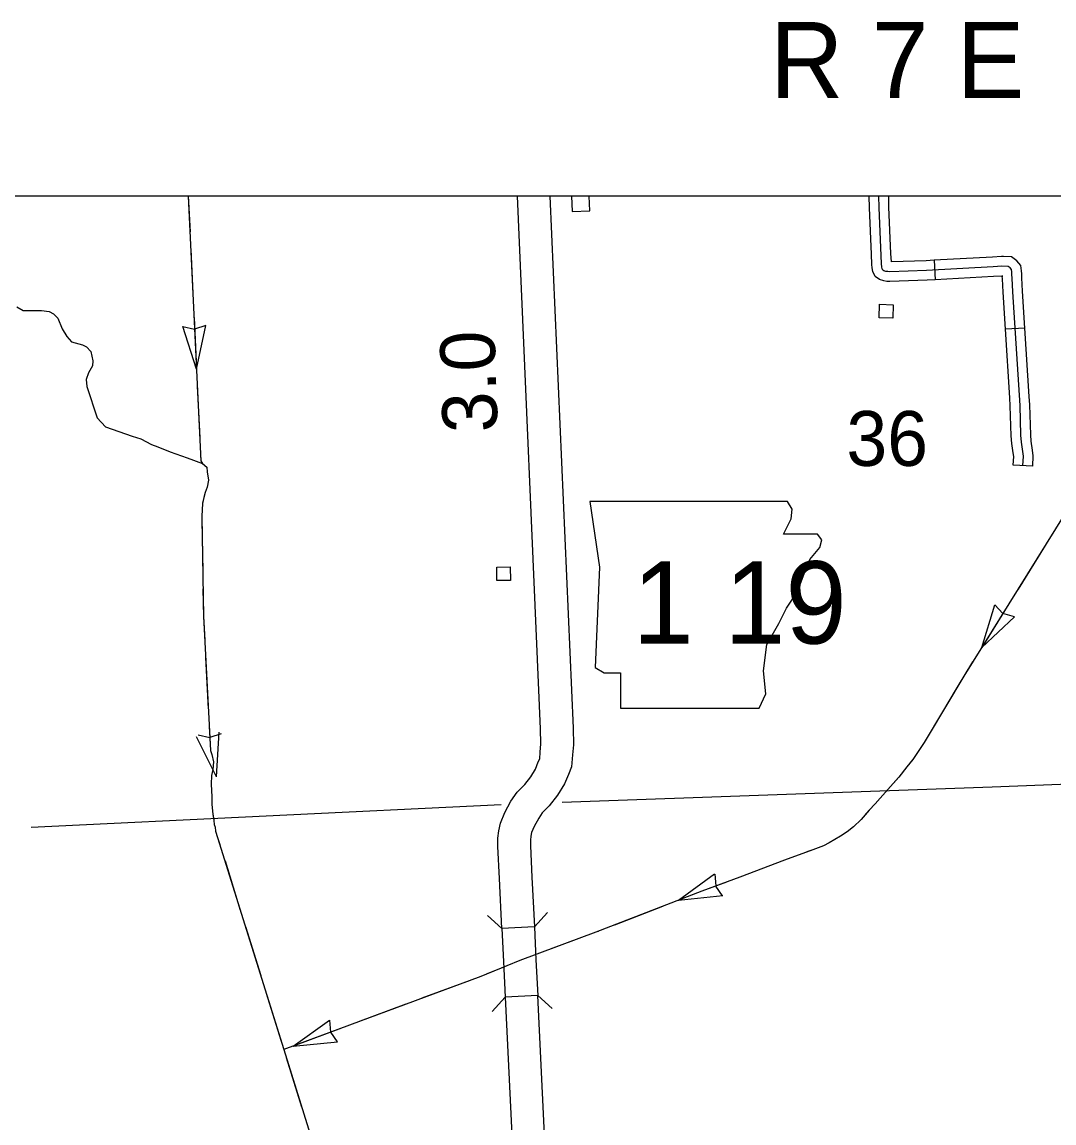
# Model space of a CAD drawing. Extents: x -0.3 to 2.65, y 0 to 1.9.
# Drawn here: x 0.767 to 0.8619, y 0.4564 to 0.5577 of the extents above; entities that cross this region are included whole.
import ezdxf

# ---------------------------------------------------------------- set-up
doc = ezdxf.new("R2010")
doc.units = 0
for name, color, linetype in [('DSN_DRFT_DNC', 7, 'Continuous'), ('Level 11', 7, 'Continuous'), ('Level 12', 7, 'Continuous'), ('Level 13', 7, 'Continuous'), ('Level 14', 7, 'Continuous'), ('Level 16', 7, 'Continuous'), ('Level 19', 7, 'Continuous'), ('Level 20', 7, 'Continuous'), ('Level 21', 7, 'Continuous'), ('Level 22', 7, 'Continuous'), ('Level 30', 7, 'Continuous'), ('Level 31', 7, 'Continuous'), ('Level 6', 7, 'Continuous'), ('SHET_Annotations', 7, 'Continuous')]:
    doc.layers.add(name, color=color, linetype=linetype)

msp = doc.modelspace()

# ---------------------------------------------------------------- linework, layer by layer
at = {"layer": 'DSN_DRFT_DNC'}
msp.add_lwpolyline([(0.38477, 0.54167), (1.0319, 0.54167), (1.0319, 0.1443), (0.38477, 0.1443)], close=True, dxfattribs=at)
at = {"layer": 'Level 11'}
for points in [[(0.81668, 0.4859), (0.85625, 0.4873), (0.87357, 0.48799)], [(0.7678, 0.48359), (0.81108, 0.48569)]]:
    msp.add_lwpolyline(points, dxfattribs=at)
at = {"layer": 'Level 12'}
for p, q in [((0.78227, 0.54164), (0.78243, 0.53836)), ((0.7839, 0.52975), (0.78285, 0.52942)), ((0.78302, 0.52574), (0.7839, 0.52975)), ((0.78302, 0.52574), (0.78177, 0.52965)), ((0.78177, 0.52965), (0.78284, 0.52942)), ((0.8553, 0.50013), (0.85649, 0.50406)), ((0.85649, 0.50406), (0.85724, 0.50326)), ((0.8553, 0.50013), (0.8583, 0.50294)), ((0.8583, 0.50294), (0.85725, 0.50326)), ((0.78486, 0.48823), (0.78512, 0.49233)), ((0.78486, 0.48823), (0.78304, 0.49191)), ((0.78318, 0.49208), (0.78425, 0.49185)), ((0.7853, 0.49219), (0.78426, 0.49185)), ((0.82738, 0.47687), (0.83069, 0.4793)), ((0.83072, 0.47928), (0.83082, 0.47819)), ((0.83145, 0.47728), (0.83082, 0.47818)), ((0.82738, 0.47687), (0.83146, 0.47732)), ((0.79192, 0.46346), (0.79527, 0.46583)), ((0.79527, 0.46583), (0.79537, 0.46475)), ((0.79601, 0.46384), (0.79538, 0.46473)), ((0.79192, 0.46346), (0.79601, 0.46384))]:
    msp.add_line(p, q, dxfattribs=at)
for points in [[(0.78227, 0.54164), (0.78342, 0.51731), (0.78358, 0.51704), (0.78397, 0.51671), (0.78402, 0.51627), (0.78412, 0.51553), (0.78402, 0.51488), (0.78381, 0.51437), (0.78371, 0.51391), (0.78358, 0.51337), (0.78352, 0.51221), (0.78366, 0.50299), (0.78432, 0.49065), (0.78445, 0.49027), (0.78458, 0.48962), (0.78454, 0.48889), (0.78441, 0.48835), (0.78439, 0.48754), (0.78445, 0.48639), (0.78445, 0.48567), (0.78453, 0.48479), (0.78462, 0.48422), (0.78464, 0.48385), (0.78475, 0.48358), (0.78478, 0.48323), (0.78497, 0.48265), (0.79106, 0.46314), (0.79518, 0.44993)], [(0.7825, 0.53678), (0.78272, 0.53205)], [(0.7828, 0.53047), (0.78302, 0.52574)], [(0.78309, 0.52416), (0.78321, 0.52179)], [(0.78321, 0.52179), (0.78332, 0.51942)], [(0.78339, 0.51785), (0.78342, 0.51731), (0.78358, 0.51704), (0.78397, 0.51671), (0.78402, 0.51627), (0.78412, 0.51553), (0.78402, 0.51488), (0.78381, 0.51437), (0.78371, 0.51391), (0.78359, 0.51342)], [(0.86537, 0.51631), (0.85366, 0.4975), (0.84999, 0.49139), (0.84895, 0.48983), (0.84839, 0.48914), (0.84768, 0.4882), (0.84665, 0.48705), (0.84549, 0.48573), (0.84494, 0.48515), (0.84419, 0.48431), (0.84349, 0.48363), (0.8429, 0.48316), (0.8423, 0.48276), (0.84125, 0.48215), (0.84074, 0.48189), (0.83976, 0.48152), (0.83715, 0.48056), (0.83303, 0.479), (0.82953, 0.47771), (0.81979, 0.47393), (0.81278, 0.47132), (0.8092, 0.46986), (0.79106, 0.46314)], [(0.78353, 0.51184), (0.7836, 0.50711)], [(0.86114, 0.50952), (0.85864, 0.5055)], [(0.78362, 0.50553), (0.78366, 0.50299), (0.78378, 0.50079)], [(0.8578, 0.50415), (0.8553, 0.50013)], [(0.78386, 0.49921), (0.78411, 0.49448)], [(0.85446, 0.49879), (0.85366, 0.4975), (0.85322, 0.49677)], [(0.85322, 0.49677), (0.852, 0.49474)], [(0.85119, 0.49339), (0.84999, 0.49139), (0.84895, 0.48983), (0.84861, 0.48941)], [(0.7842, 0.4929), (0.78432, 0.49065), (0.78445, 0.49027), (0.78458, 0.48962), (0.78454, 0.48889), (0.78441, 0.48835), (0.78441, 0.48822)], [(0.84765, 0.48817), (0.84665, 0.48705), (0.84549, 0.48573), (0.84494, 0.48515), (0.84448, 0.48464)], [(0.78444, 0.48664), (0.78445, 0.48639), (0.78445, 0.48567), (0.78453, 0.48479), (0.78461, 0.48428)], [(0.78461, 0.48428), (0.78462, 0.48422), (0.78464, 0.48385), (0.78475, 0.48358), (0.78478, 0.48323), (0.78497, 0.48265), (0.78517, 0.482)], [(0.84336, 0.48353), (0.8429, 0.48316), (0.8423, 0.48276), (0.84125, 0.48215), (0.84074, 0.48189), (0.83976, 0.48152), (0.8392, 0.48132)], [(0.78565, 0.48049), (0.78706, 0.47597)], [(0.83772, 0.48077), (0.83715, 0.48056), (0.83329, 0.4791)], [(0.83181, 0.47855), (0.82953, 0.47771), (0.82738, 0.47687)], [(0.8259, 0.4763), (0.8237, 0.47544)], [(0.8237, 0.47544), (0.82149, 0.47459)], [(0.78753, 0.47446), (0.78894, 0.46994)], [(0.82001, 0.47401), (0.81979, 0.47393), (0.81557, 0.47236)], [(0.81131, 0.47072), (0.80969, 0.47006)], [(0.80821, 0.4695), (0.80377, 0.46785)], [(0.78941, 0.46843), (0.79082, 0.4639)], [(0.80229, 0.4673), (0.79785, 0.46565)], [(0.79637, 0.46511), (0.79192, 0.46346)], [(0.79129, 0.4624), (0.7927, 0.45787)]]:
    msp.add_lwpolyline(points, dxfattribs=at)
at = {"layer": 'Level 13'}
for p, q in [((0.85092, 0.53575), (0.85101, 0.53396)), ((0.85927, 0.52951), (0.85748, 0.5294)), ((0.85999, 0.51681), (0.8582, 0.5169))]:
    msp.add_line(p, q, dxfattribs=at)
for points in [[(0.84515, 0.5363), (0.84497, 0.54057), (0.84493, 0.54164)], [(0.85909, 0.51685), (0.85914, 0.51773), (0.85909, 0.51816), (0.85896, 0.519), (0.8589, 0.51965), (0.85882, 0.5224), (0.85817, 0.53285), (0.85811, 0.53409), (0.85808, 0.53444), (0.85807, 0.53469), (0.85804, 0.53489), (0.85791, 0.53504), (0.85773, 0.53517), (0.85713, 0.5352), (0.85634, 0.53515), (0.85021, 0.53481), (0.84685, 0.53469), (0.84665, 0.5347), (0.84648, 0.53472), (0.84629, 0.53478), (0.84619, 0.53485), (0.84613, 0.53497), (0.84611, 0.53515), (0.84608, 0.53543), (0.84587, 0.5406), (0.84583, 0.54164)], [(0.84694, 0.53638), (0.84676, 0.54064), (0.84673, 0.54164)], [(0.85101, 0.53396), (0.85026, 0.53392), (0.84684, 0.53379), (0.84655, 0.5338), (0.84628, 0.53385), (0.84589, 0.53397), (0.84548, 0.53425), (0.84526, 0.53471), (0.84522, 0.53505), (0.84519, 0.53537), (0.84515, 0.5363)], [(0.85092, 0.53575), (0.85017, 0.53571), (0.84698, 0.53559), (0.84694, 0.53638)], [(0.85731, 0.53609), (0.85712, 0.53609), (0.85629, 0.53604), (0.85092, 0.53575)], [(0.85927, 0.52951), (0.85906, 0.5329), (0.859, 0.53414), (0.85898, 0.53449), (0.85896, 0.53479), (0.85888, 0.53528), (0.85852, 0.5357), (0.85804, 0.53606), (0.85731, 0.53609)], [(0.85724, 0.53429), (0.85714, 0.5343), (0.85639, 0.53425), (0.85101, 0.53396)], [(0.85748, 0.5294), (0.85727, 0.5328), (0.85721, 0.53404), (0.85719, 0.53429), (0.85724, 0.53429)], [(0.85787, 0.5231), (0.85748, 0.5294)], [(0.85966, 0.52321), (0.85927, 0.52951)], [(0.8582, 0.5169), (0.85824, 0.51771), (0.8582, 0.51804), (0.85806, 0.51889), (0.85801, 0.5196), (0.85792, 0.52236), (0.85787, 0.5231)], [(0.85999, 0.51681), (0.86004, 0.51776), (0.85998, 0.51828), (0.85985, 0.51911), (0.8598, 0.5197), (0.85971, 0.52244), (0.85966, 0.52321)]]:
    msp.add_lwpolyline(points, dxfattribs=at)
at = {"layer": 'Level 14'}
msp.add_lwpolyline([(0.7665, 0.53147), (0.76707, 0.53112), (0.76796, 0.53112), (0.76877, 0.53112), (0.76946, 0.53104), (0.76988, 0.53083), (0.77026, 0.53042), (0.77067, 0.52945), (0.77108, 0.52874), (0.77151, 0.52824), (0.77252, 0.52796), (0.7729, 0.52777), (0.7733, 0.52734), (0.77349, 0.52651), (0.77347, 0.52603), (0.77309, 0.52538), (0.77286, 0.52477), (0.77294, 0.52415), (0.77389, 0.52125), (0.77464, 0.52042), (0.7771, 0.51958), (0.7779, 0.51932), (0.77889, 0.51881), (0.77946, 0.51857), (0.7806, 0.51812), (0.78218, 0.51757), (0.78358, 0.51704)], dxfattribs=at)
at = {"layer": 'Level 19'}
for points in [[(0.84714, 0.53166), (0.8471, 0.53042), (0.84585, 0.53046), (0.8459, 0.53171)], [(0.81191, 0.50754), (0.81193, 0.50629), (0.81068, 0.50628), (0.81067, 0.50752)]]:
    msp.add_lwpolyline(points, close=True, dxfattribs=at)
at = {"layer": 'Level 21'}
for points in [[(0.81113, 0.47427), (0.8109, 0.47887), (0.81076, 0.48181), (0.81076, 0.48257), (0.81084, 0.48325), (0.81099, 0.48397), (0.81139, 0.48495), (0.81197, 0.48599), (0.81253, 0.48682), (0.81323, 0.48753), (0.81379, 0.48824), (0.81422, 0.48893), (0.81448, 0.4896), (0.81461, 0.48989), (0.81466, 0.49049), (0.81471, 0.49126), (0.8147, 0.49263), (0.81256, 0.54164)], [(0.81555, 0.54164), (0.81769, 0.49271), (0.81771, 0.49118), (0.81764, 0.49026), (0.81755, 0.48915), (0.81725, 0.48845), (0.8169, 0.48758), (0.81625, 0.48653), (0.81549, 0.48555), (0.81484, 0.48491), (0.81452, 0.48442), (0.81409, 0.48365), (0.81386, 0.48309), (0.8138, 0.48277), (0.81376, 0.48241), (0.81376, 0.48188), (0.81389, 0.47901), (0.81412, 0.47442), (0.81113, 0.47427)], [(0.81113, 0.47427), (0.81129, 0.47124), (0.81144, 0.46796)], [(0.81412, 0.47442), (0.81427, 0.47139), (0.81443, 0.4681)], [(0.81443, 0.4681), (0.81144, 0.46796), (0.81373, 0.42057), (0.81434, 0.40771), (0.81519, 0.38928), (0.81551, 0.37423), (0.81555, 0.37264), (0.81855, 0.37272)], [(0.81855, 0.37272), (0.8185, 0.3743), (0.81818, 0.38938), (0.81733, 0.40785), (0.81672, 0.42071), (0.81443, 0.4681)]]:
    msp.add_lwpolyline(points, dxfattribs=at)
at = {"layer": 'Level 22'}
msp.add_lwpolyline([(0.81922, 0.51357), (0.82013, 0.5075), (0.81973, 0.49829), (0.82054, 0.49778), (0.82206, 0.49778), (0.82206, 0.49454), (0.83481, 0.49454), (0.83542, 0.49586), (0.83522, 0.49799), (0.83552, 0.50041), (0.83663, 0.50234), (0.83734, 0.50375), (0.83835, 0.50527), (0.83896, 0.50689), (0.83947, 0.50821), (0.84038, 0.50932), (0.84058, 0.51003), (0.84018, 0.51054), (0.83704, 0.51054), (0.83775, 0.51195), (0.83785, 0.51286), (0.83743, 0.51356)], close=True, dxfattribs=at)
at = {"layer": 'Level 30'}
for points in [[(0.81113, 0.47427), (0.8098, 0.47547)], [(0.81532, 0.47575), (0.81412, 0.47442)], [(0.81024, 0.46663), (0.81144, 0.46796)], [(0.81443, 0.4681), (0.81576, 0.4669)]]:
    msp.add_lwpolyline(points, dxfattribs=at)
at = {"layer": 'Level 31'}
msp.add_lwpolyline([(0.81755, 0.54164), (0.81761, 0.54023), (0.81922, 0.5403), (0.81916, 0.54164)], dxfattribs=at)
at = {"layer": 'Level 6'}
msp.add_lwpolyline([(1.03189, 0.54164), (1.03189, 0.54164), (0.38476, 0.54164)], dxfattribs=at)

# ---------------------------------------------------------------- texts
at = {"layer": 'Level 16'}
msp.add_text('3.0', height=0.00505, rotation=91.8551, dxfattribs=at).set_placement((0.81075, 0.51997))
at = {"layer": 'Level 20'}
msp.add_text('36', height=0.00505, dxfattribs=at).set_placement((0.84284, 0.51683))
at = {"layer": 'Level 22'}
msp.add_text('1 19', height=0.007575, dxfattribs=at).set_placement((0.82315, 0.50048))
at = {"layer": 'SHET_Annotations'}
msp.add_text('R 7 E', height=0.007, dxfattribs=at).set_placement((0.83581, 0.55067))

doc.saveas('drawing.dxf')
